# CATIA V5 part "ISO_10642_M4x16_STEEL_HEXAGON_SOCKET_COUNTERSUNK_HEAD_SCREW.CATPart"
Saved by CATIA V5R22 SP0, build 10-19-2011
Part number: ISO 10642 SCREW M4x16 STEEL HEXAGON SOCKET COUNTERSUNK HEAD
Publications: "Mating Edge", "Axis"
Bounding box of the stored display mesh (mm): x -16.35 to 0, y -4.479 to 4.479, z -4.479 to 4.479
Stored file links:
  D:\PER\CAO_PER_MODIF_2025\CAO_PER_pick&place_2024P\Sous_Ensemble_Flacon\ISO_10642_M4x16_STEEL_HEXAGON_SOCKET_COUNTERSUNK_HEAD_SCREW.CATPart
  C:\Program Files\Dassault Systemes\B22\win_b64\startup\components\MechanicalStandardParts\EN_Standards\Design_Tables\EN_ISO_10642_HEXAGON_SOCKET_COUNTERSUNK_SCREW.txt
  C:\Program Files\Dassault Systemes\B22\win_b64\startup\components\MechanicalStandardParts\ISO_Standards\Design_Tables\ISO_10642_HEXAGON_SOCKET_COUNTERSUNK_SCREW.txt
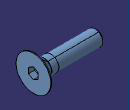
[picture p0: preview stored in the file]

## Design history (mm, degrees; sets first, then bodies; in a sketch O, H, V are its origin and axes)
Parameters
  l_length_nom = 16 mm
  b_ref = 20
  l_length_min = 15.65 mm
  l_length_max = 16.35 mm
  dk_head_dia_max = 8.96 mm
  dk_head_dia_min = 7.53 mm
  ls = 4.58 mm
  k_hed_depth = 2.48 mm
  r = 0.2 mm
  s_across_flats = 2.5 mm
  t_insert_depth = 1.5 mm
  d_dia = 4 mm
  threading = 11.42 mm
  p_pitch = 0.7 mm
Body1 "PartBody" (main body)
  Sketch1 on zx-plane, origin (0, 0, 0), H (-1, 0, 0), V (0, 0, 1)
    line L1 (0, 4.48) -> (0.2333, 4.48)
    point P2 (0.2333, 4.48)
    line L2 (0.2333, 4.48) -> (2.7133, 2)
    line L3 (2.7133, 2) -> (4.58, 2)
    line L4 (4.58, 2) -> (4.58, 1.9512)
    point P5 (4.58, 1.9512)
    line L5 (4.58, 1.9512) -> (15.9711, 1.9512)
    point P6 (15.9711, 1.9512)
    line L6 (15.9711, 1.9512) -> (16.35, 1.5723)
    axis line L7 (-30, 0) -> (125, 0)
    line L8 (16.35, 1.5723) -> (16.35, 0)
    point P10 (16.35, 0)
    line L9 (0, 4.48) -> (0, 0)
    distance L9 P5 = 4.58 {= ls}
    distance L9 L8 = 16.35 {= l_length_max}
    angle L5 L6 = 45
    distance L5 L7 = 1.9512 {= d_dia /2.05}
    distance L3 L7 = 2 {= d_dia  /2}
    angle L7 L2 = 45
    distance L1 L7 = 4.48 {= dk_head_dia_max /2}
    distance L9 P2 = 0.2333 {= p_pitch /3}
    distance P6 L8 = 0.3789 {= p_pitch *0.5413}
    horizontal: L1 H, L3 H, L5 H, L7 H
    vertical: L4 V, L9 V
    fix: L7
    coincidence: P10 L7
  Shaft1: profile Sketch1, axis Sketch1.L7, angle 360
  Body2
    Sketch2 on face of Shaft1, origin (0, 0, 0), H (0, 1, 0), V (0, 0, 1)
      point P1 (1.25, -0.7217)
      point P2 (1.25, 0.7217)
      point P3 (0, 1.4434)
      point P4 (-1.25, 0.7217)
      point P5 (-1.25, -0.7217)
      point P6 (0, -1.4434)
      point P7 (1.25, 0)
      line L1 (1.25, -0.7217) -> (1.25, 0.7217)
      line L2 (1.25, 0.7217) -> (0, 1.4434)
      line L3 (0, 1.4434) -> (-1.25, 0.7217)
      line L4 (-1.25, 0.7217) -> (-1.25, -0.7217)
      line L5 (-1.25, -0.7217) -> (0, -1.4434)
      line L6 (0, -1.4434) -> (1.25, -0.7217)
      construction line L7 (0, 0) -> (1.25, 0)
      construction circle A1 centre (0, 0) radius 1.4434
      construction arc A2 centre (-1.25, -0.7217) radius 1.4434 from (-1.25, 0.7217) to (0, -1.4434) cw
      construction arc A3 centre (1.25, 0.7217) radius 1.4434 from (0, 1.4434) to (1.25, -0.7217) ccw
      point P8 (-1.25, -0.7217)
      point P9 (1.25, 0.7217)
      distance L1 L4 = 2.5 {= s_across_flats}
      horizontal: L7 H
      coincidence: A1 P1, A1 P2, A1 P3, A1 P4, A1 P5, A1 P6, A2 P4, A2 P6, A2 O, P8 P5, A3 P3, A3 P1, A3 O, P9 P2
      midpoint: P7 L1
    Pad1: profile Sketch2, direction (-1, 0, 0), length 20
    Body3
      Sketch3 on zx-plane, origin (0, 0, 0), H (-1, 0, 0), V (0, 0, 1)
        line L1 (0, 0) -> (0, 1.4434)
        line L2 (0, 1.4434) -> (1.5, 1.4434)
        point P2 (1.5, 1.4434)
        line L3 (1.5, 1.4434) -> (2.3333, 0)
        point P3 (2.3333, 0)
        axis line L4 (-13.9938, 0) -> (46.4324, 0)
        reference projected line E1 (0, 1.4434) -> (20, 1.4434) from edge [face of Pad1 | face of Pad1]
        angle L3 L4 = 60
        distance L1 P2 = 1.5 {= t_insert_depth}
        vertical: L1 V
        horizontal: L2 H, L4 H
        fix: L4
        coincidence: L2 E1, P3 L4
      Shaft2: profile Sketch3, axis Sketch3.L4, angle 360
    Intersect1: tool Body3
  Remove1: tool Body2
  Fillet1: radius 0.2 {= r}, on edge [face of Shaft1 | face of Shaft1]
  Thread1: diameter 3.9024 {= d_dia /1.025}, depth 11.42 {= threading}, pitch 1, on face of Shaft1, from face of Shaft1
